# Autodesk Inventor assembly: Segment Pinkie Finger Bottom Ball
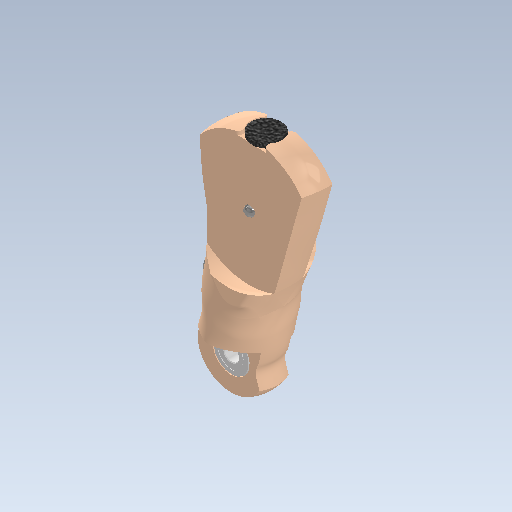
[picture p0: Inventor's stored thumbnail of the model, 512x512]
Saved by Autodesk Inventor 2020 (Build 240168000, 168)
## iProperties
Created: 2019-10
Part Number: Segment Pinkie Finger Bottom Ball
Document SubType Name: Assembly
Designer: yello
Author: yello
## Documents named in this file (8)
- D:\1-Cours-2021-22\1STI2D\ETLV\AI\Prototype 2 (Realistic Hand)\Segment Pinkie Finger Bottom Ball.iam
- D:\1-Cours-2021-22\1STI2D\ETLV\AI\Prototype 2 (Realistic Hand)\Segment Pinkie Finger Bottom.ipt
- D:\1-Cours-2021-22\1STI2D\ETLV\AI\Prototype 2 (Realistic Hand)\Lock.ipt
- D:\1-Cours-2021-22\1STI2D\ETLV\AI\Prototype 2 (Realistic Hand)\Ball.ipt
- D:\1-Cours-2021-22\1STI2D\ETLV\AI\Prototype 2 (Realistic Hand)\Plug 3.ipt
- D:\1-Cours-2021-22\1STI2D\ETLV\AI\Prototype 2 (Realistic Hand)\Push Part.ipt
- D:\1-Cours-2021-22\1STI2D\ETLV\AI\Prototype 2 (Realistic Hand)\Spring.ipt
- D:\1-Cours-2021-22\1STI2D\ETLV\AI\Prototype 2 (Realistic Hand)\Bearings.iam
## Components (8 placed, 7 different names)
1. Segment Pinkie Finger Bottom:1 — Mate:5, Mate:6, Mate:9, Mate:10, Mate:11, Mate:12, Mate:13, Mate:14, Flush:1
2. Ball:1 — Mate:6
3. Ball:2 — Mate:5
4. Push Part:1 — Mate:7, Mate:8, Mate:9
5. Lock:1 — Mate:7, Mate:8, Mate:10
6. Spring:1 — Mate:11
7. Plug 3:1 — Mate:12, Mate:13
8. Bearings:1 [sub-assembly] — Mate:14, Flush:1
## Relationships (11: Mate 10, Flush 1)
- Mate:5: Segment Pinkie Finger Bottom:1 ↔ Ball:2
- Mate:6: Segment Pinkie Finger Bottom:1 ↔ Ball:1
- Mate:7: Push Part:1 ↔ Lock:1
- Mate:8: Push Part:1 ↔ Lock:1
- Mate:9: Segment Pinkie Finger Bottom:1 ↔ Push Part:1
- Mate:10: Segment Pinkie Finger Bottom:1 ↔ Lock:1
- Mate:11: Segment Pinkie Finger Bottom:1 ↔ Spring:1
- Mate:12: Segment Pinkie Finger Bottom:1 ↔ Plug 3:1
- Mate:13: Segment Pinkie Finger Bottom:1 ↔ Plug 3:1
- Mate:14: Segment Pinkie Finger Bottom:1 ↔ Bearings:1
- Flush:1: Segment Pinkie Finger Bottom:1 ↔ Bearings:1
